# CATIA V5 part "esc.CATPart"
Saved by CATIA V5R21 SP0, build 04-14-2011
Part number: esc
Material "Chroma": density 7190 kg/m3, Young's modulus 7e+10 Pa, Poisson ratio 0.3, thermal expansion 6.2e-06 1/K
Bounding box of the stored display mesh (mm): x -80 to 80, y -31.5 to 31.5, z -15 to 15
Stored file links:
  C:\Users\rodri\OneDrive\Área de Trabalho\FACULDADE\3°semestre\Sistemas Aeroespaciais\Projeto de avião 2019-02\CAD\esc.CATPart
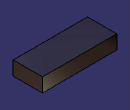
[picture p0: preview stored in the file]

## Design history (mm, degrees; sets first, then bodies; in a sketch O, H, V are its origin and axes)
Body1 (main body), material "Chroma"
  Sketch1 on xy-plane, origin (0, 0, 0), H (1, 0, 0), V (0, 1, 0)
    line L1 (-80, 31.5) -> (80, 31.5)
    line L2 (80, 31.5) -> (80, -31.5)
    line L3 (80, -31.5) -> (-80, -31.5)
    line L4 (-80, -31.5) -> (-80, 31.5)
    length L3 = 160
    length L4 = 63
    horizontal: L1 H, L3 H
    vertical: L2 V, L4 V
    symmetry: L4 L2 V, L3 L1 H
  Pad1: profile Sketch1, direction (0, 0, 1), length 15, mirrored extent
